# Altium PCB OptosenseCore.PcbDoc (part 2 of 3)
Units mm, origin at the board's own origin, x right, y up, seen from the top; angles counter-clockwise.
Board outline 65 x 56 mm, 4 copper layers (Top, Signal Layer 1, Power Layer 2, Bottom), stack 0.844 mm thick; 184 components, 119 nets, 728 pads, 633 vias.
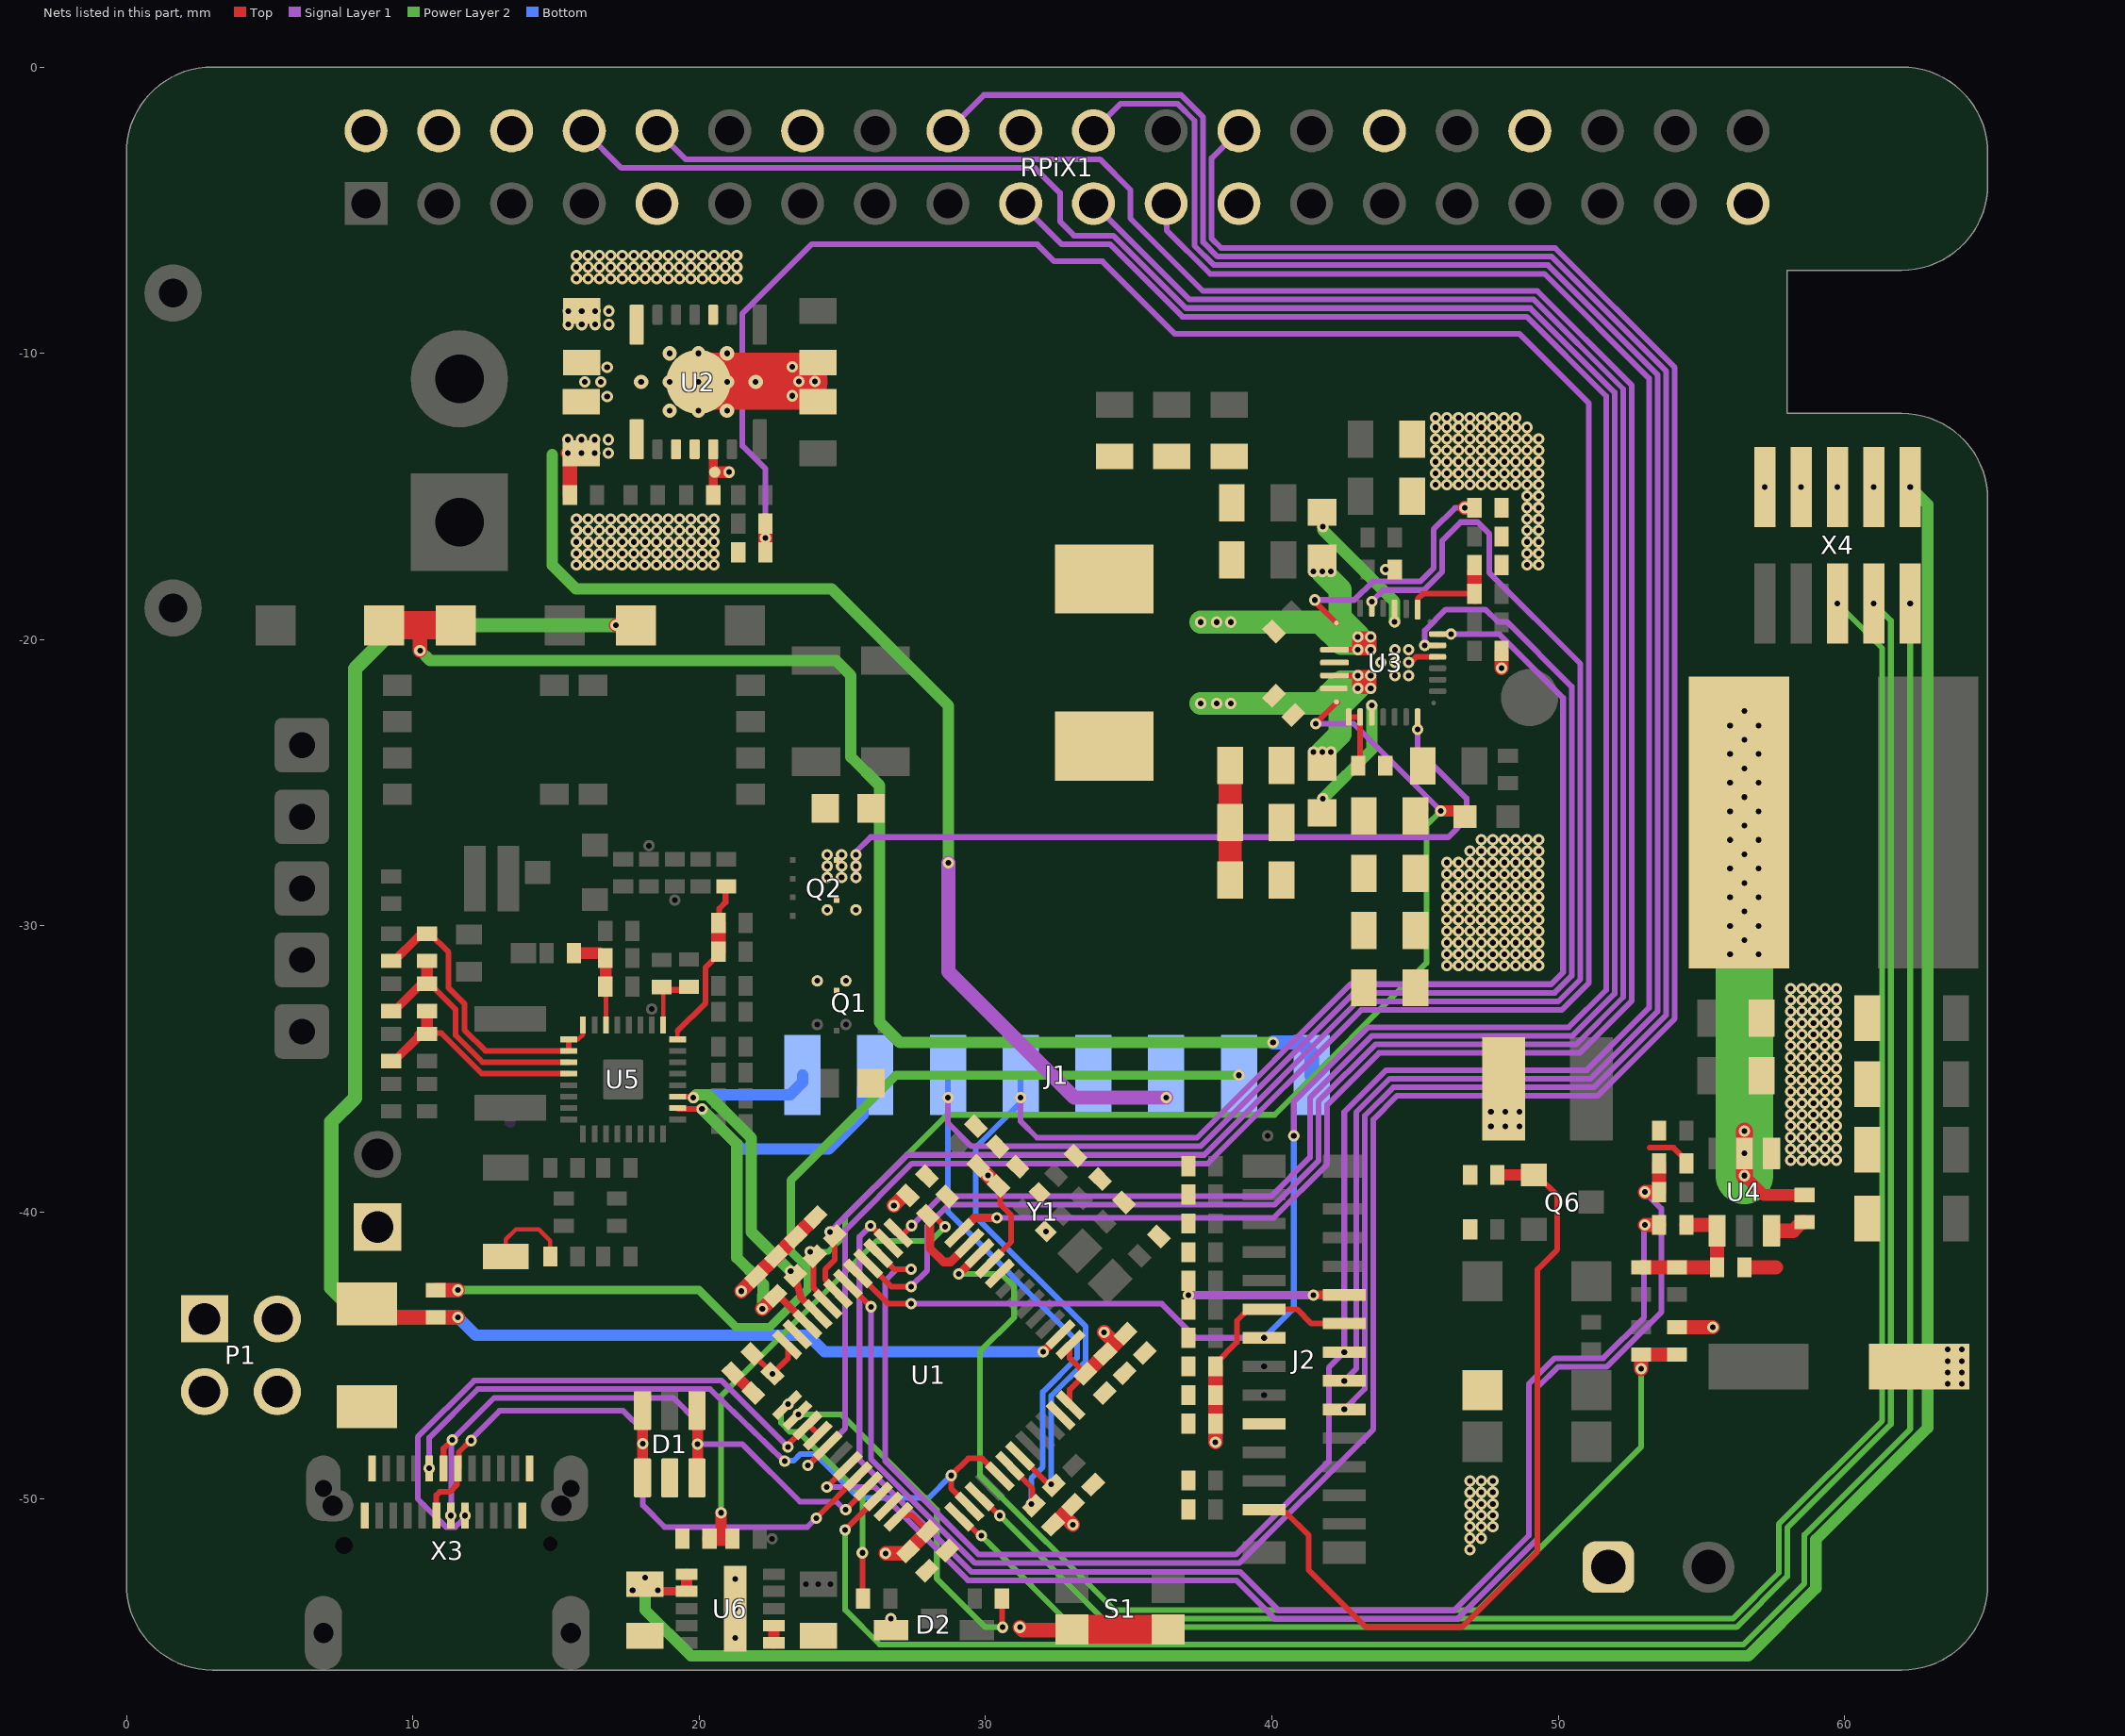
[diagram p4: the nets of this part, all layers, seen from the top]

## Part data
C1 C2 C3 C4 C5 C6 C7 C8 C9 C10 C11 C12 C13 C14 C15 C16 C24 C34 C35 C38 C41 C45 C48 C54 C55 C56 C57 C58 C59 C60 C61 C62 C64 C67 C68 C69 C70 C71 C72 C74: library part C_X_0402
C17 C18: library part C_X_0603
C19 C20 C21 C22 C25 C26 C27 C28 C29 C30 C31 C32 C33 C36 C37 C40 C42 C43 C44 C46 C47 C63 C65: library part C_X_0805
C49 C50 C51 C52: library part C_X_1206
C53: library part 865080543009, "WCAP-ASLI Aluminum Electrolytic Capacitor, V-Chip, SMT, D6.3xH5.5mm, 47uF, 35V", Capacitance Tolerance=+/-20%, Leakage Current=16.45uA, Manufacturer="Wurth Elektronik", Operating Temperature="-55 to +105degC", Rated Voltage=35VDC, Ripple Current=240mA
C66: library part C_X_1210
C73 C75 C76 C77 C78 C79 C80 C81 C82 C83: library part C_X_0402, "50V"
D1: "17V Clamp 5A _8/20Âµs_ Ipp Tvs Diode Surface Mount SOT-23-6", Package="SOT-23-6 STMicroelectronics"
D2: library part 155124RG73200, "WL-SBSW SMT Bi-color Side View Waterclear, size 1204, Red & Green, 120deg", Emitting Color="Red & Green", Forward Voltage="3.3V@Green, 2V@Red", Operating Temperature="-40 to +85degC"
D3 D4: library part D_Zener_SOD-80_12V, "12V BZT55C12-GS08"
D5: "Green 569nm LED Indication - Discrete 2.1V 0603 (1608 Metric)", Package="0603 Lite-On"
D6 D8 D9 D10 D11 D12: "BAT54W-HG3-08"
D7: library part D_Schottky_SOD323_BAS40WT
DZ1: "Zener Diode 3.3V 500mW Â±5% Surface Mount SOD-123", Package="SOD-123 Fairchild Semiconductor"
J2: library part 687324124422, "WR-FPC SMT ZIF Vertical, pitch 0.5mm, 24p", Contact Resistance=20mOhm, Operating Temperature="-25 to +85degC", Rated Current=0.5A, Working Voltage=50VAC
J_Interlock1: "WR-TBL Serie 1031 Horizontal Entry Modular, Pressure Clamp, THT, pitch 3.5mm, 2p", Manufacturer="Wurth Elektronik", Operating Temperature="-40 to +105degC", Rated Current [UL]=10A, Working Voltage [UL]=125VAC
L1: library part L_2u2_KEMET, "MPXV1D0630L2R2"
L2: library part L_18u, "744066180"
L3: library part 74404041680, "WE-LQS SMT Power Inductor, size 4012, 68µH, 0.45A, 1.495Ω", Case/Size Code=4012, DC Resistance=1.495Ω, Inductance=68µH, Manufacturer="Wurth Elektronik", Operating Temperature Max=125°C, Operating Temperature Min=-40°C, Rated Current=0.45A, Saturation Current=0.48A, Self Resonant Frequency=13MHz
NT1 NT2: library part "Net Tie"
P1: "WR-PHD Pin Header, THT, pitch 2.54mm, Dual Row, Vertical, 4p", Contact Resistance=20mOhm, Manufacturer="Wurth Elektronik", Operating Temperature="-40 to +105degC", Rated Current=3A, Withstanding Voltage=500VAC, Working Voltage=250VAC
P2: "WR-PHD Pin Header, THT, pitch 2.54mm, Single Row, Angled, 2p", Contact Resistance=20mOhm, Manufacturer="Wurth Elektronik", Operating Temperature="-40 to +105degC", Rated Current=3A, Withstanding Voltage=500VAC, Working Voltage=250VAC
Q1 Q2: "30V, N ch NexFET MOSFET, dual common source SON3x3, 21.9mOhm 8-VSON -55 to 150", Package="VSON-8 Texas Instruments"
Q3: library part Q_P-Channel_MOSFET_DMP3098LQ-7
Q4 Q5: library part Q_N-Channel_MOSFET_SO-8FL_NTMFS4C029NT1G
Q6: library part NTR4170NT1G
R1 R2 R3 R4 R5 R6 R7 R8 R9 R10 R11 R12 R13 R14 R15 R16 R17 R18 R19 R20 R21 R22 R23 R24 R25 R26 R27 R28 R29 R30 R31 R33 R34 R35 R36 R37 R38 R39 R40 R41 R42 R43 R44 R45 R46 R47 R48 R49 R50 R51 R52 R53 R54 R56 R57: library part R_X_0402
R32: library part R_X_0508
R55: library part R_X_1206
RPiX1: library part RPi, "WR-PHD Socket Header, SMT, pitch 2.54mm, Dual Row, Vertical, 40pin", Contact Resistance=20mOhm, Operating Temperature="-40 to +105degC", Part Number=61004021821, Rated Current=3A, Withstanding Voltage=600VAC, Working Voltage=250VAC
S1: "WS-TASV J-Bend SMT Tact Switch, 3.5x2.9x1.7mm, 350gf", Manufacturer="Wurth Elektronik", Operating Temperature="-40 to +85degC", Rated Current=50mA, Rated Voltage=12VDC
TP1: library part Testpoint, "Testpoint"
U1: library part STM32L552CCXX
U2: "No Description Available"
U3: library part BQ25792, "Battery Charger IC, QFN (29) _4x4_"
U4: library part IC_TPS54302
U5: library part IC_BQ40z80
U6: "4V to 36V, 1A Step-Down Converter Module With Integrated Inductor in 3x3.8x1.6mm Package 10-uSiP -40 to 125", Package=None
X1: library part X_XH5
X2: library part X_XT30PB-F-90°, "XT30PB-F-90°"
X3: library part X_USB_TypC
X4: library part X_Cortex_Debug_10
Y1: library part 830072539, "WE-XTAL Quartz Crystal, SMT, IQXC-26, 24MHz, +/-15ppm", Frequency Stability=+/-15ppm, Load Capacitance=8pF, Manufacturer="Wurth Elektronik", Operating Temperature="-20 to +70degC"
Y2: library part NX2012SA-32.768K-STD-MUB-1, "32.768kHz Â±20ppm Crystal 12.5pF 80 kOhms 2-SMD, No Lead", Package="SMD-2 NDK"

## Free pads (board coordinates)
  round 0.4 hole 0.2 mask+0: 3(10.575,-48.95) 3(11.325,-50.6) 3(11.825,-50.6) 3(17.678,-53.213) 3(18.11,-52.769) 3(18.25,-27.2) 3(18.346,-32.907) 3(18.561,-53.213) 3(19.15,-29.1) 3(19.8,-36) 3(20.1,-36.4) 3(20.764,-50.5) 3(21.475,-42.76) 3(22.207,-43.375) 3(22.548,-51.41) 3(22.56,-45.648) 3(22.987,-48.7) 3(23.1,-48.2) 3(23.11,-46.709) 3(23.195,-42.066) 3(23.464,-47.062) 3(23.724,-52.997) 3(23.879,-41.383) 3(24.165,-52.997) 3(24.574,-40.688) 3(24.587,-52.997) 3(25.1,-51.1) 3(26.508,-51.918) 3(26.802,-39.771) 3(28.69,-36) 3(30.081,-38.722) 3(31.23,-36) 3(33.055,-50.914) 3(34.145,-44.196) 3(37.515,-22.234) 3(37.515,-19.391) 3(38.071,-22.234) 3(38.071,-19.391) 3(38.563,-22.234) 3(38.563,-19.391) 3(38.85,-35.217) 3(39.73,-46.392) 3(39.73,-45.392) 3(39.73,-44.392) 3(39.853,-37.333) 3(40.042,-34.072) 3(40.767,-37.333) 3(41.453,-23.927) 3(41.453,-17.628) 3(41.758,-23.927) 3(41.758,-17.628) 3(41.783,-25.555) 3(41.783,-16.055) 3(42.062,-23.927) 3(42.062,-17.628) 3(42.53,-46.892) 3(42.53,-45.892) 3(42.53,-44.892) 3(43.004,-21.705) 3(43.004,-21.255) 3(43.004,-20.355) 3(43.004,-19.905) 3(43.451,-21.705) 3(43.451,-21.255) 3(43.451,-20.355) 3(43.451,-19.905) 3(43.488,-22.301) 3(44.288,-19.38) 3(45.339,-20.205) 3(46.253,-19.805) 3(47.65,-37) 3(47.65,-36.5) 3(48.15,-37) 3(48.15,-36.5) 3(48.65,-37) 3(48.65,-36.5)

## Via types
v1: diameter 0.4, hole 0.2, Top to Bottom, tented both sides, 616 vias
v2: diameter 0.5, hole 0.2, Top to Bottom, tented bottom, 11 vias
v3: diameter 4, hole 2.75, Top to Bottom, 4 vias
v4: diameter 0.4, hole 0.2, Top to Bottom, tented bottom, 1 vias
v5: diameter 0.6, hole 0.3, Top to Bottom, tented bottom, 1 vias

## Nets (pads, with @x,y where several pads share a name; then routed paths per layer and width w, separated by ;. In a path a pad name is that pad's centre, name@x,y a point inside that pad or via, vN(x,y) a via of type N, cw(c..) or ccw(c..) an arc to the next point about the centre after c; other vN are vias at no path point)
3V3: C7.2 C8.2 C9.2 C10.2 C11.2 C12.2 C13.2 C14.2 C15.2 C16.2 C63.2 C72.2 C73.2 C74.2 D2.2 J2.15 J2.16 L3.1 pad.3@17.678,-53.213 pad.3@18.11,-52.769 pad.3@18.561,-53.213 pad.3@21.475,-42.76 pad.3@22.56,-45.648 pad.3@26.508,-51.918 pad.3@26.802,-39.771 pad.3@30.081,-38.722 pad.3@33.055,-50.914 pad.3@34.145,-44.196 pad.3@47.65,-36.5 pad.3@47.65,-37 pad.3@48.15,-36.5 pad.3@48.15,-37 pad.3@48.65,-36.5 pad.3@48.65,-37 R5.1 R6.1 R7.1 R8.2 R9.1 R10.2 S1.2 S1.4 U1.1 U1.9 U1.24 U1.36 U1.48 U6.6 U6.7 X4.1 | length 119.9
  Top w0.2: C9.2@21.86,-44.948 C10.2@22.56,-45.648 23.11,-45.098 U1.24@23.11,-44.658 ; U1.36@26.999,-50.598 27.439,-50.598 C11.2@27.989,-51.148 ; U1.9@30.146,-41.794 30.9,-41.04 30.9,-40.102 30.522,-39.724 30.522,-39.31 C7.2@30.599,-39.232 ; U1.48@32.939,-46.709 32.939,-46.197 C13.2@33.489,-45.648 32.939,-45.098 U1.1@32.939,-44.658 ; C72.2@38.032,-45.39 38.032,-45.29 38.78,-44.542 38.78,-43.966 38.782,-43.964 38.782,-43.79 39.18,-43.392 40.88,-43.392 41.38,-43.892 J2.15@42.53,-43.892
  Top w0.3: C63.2@18.11,-52.997 18.36,-53.247 U6.7@19.56,-53.247 ; R6.1@23.323,-40.817 R6.1@23.332,-40.817
  Top w0.4: U6.7@19.56,-53.247 U6.6@19.56,-52.647
  Top w0.5: pad.3@21.477,-42.759 R10.2@21.989,-42.248 R9.1@22.689,-41.548 R6.1@23.323,-40.913 ; R6.1@23.421,-40.815 R7.1@24.056,-40.181 ; pad.3@26.508,-51.918 27.218,-51.918 C12.2@27.289,-51.848 27.918,-51.218 C11.2@27.989,-51.148 ; pad.3@26.803,-39.763 27.218,-39.349 C16.2@27.289,-39.419 ; C8.2@29.899,-38.532 pad.3@30.085,-38.718 ; pad.3@30.081,-38.722 30.089,-38.722 C7.2@30.452,-39.084 ; v1(31.2,-54.5) 31.3,-54.6 32.997,-54.6 S1.2@33.025,-54.572 ; R5.1@32.36,-50.919 32.431,-50.849 32.746,-50.534 ; pad.3@33.055,-50.914 32.746,-50.605 32.746,-50.534 ; R8.2@33.06,-50.219 32.746,-50.534 ; C13.2@33.489,-45.648 33.559,-45.577 C14.2@34.189,-44.948 34.543,-44.593 ; pad.3@34.145,-44.196 34.543,-44.593 ; C15.2@34.889,-44.248 34.543,-44.593 ; v1(38.032,-48.04) C74.2@38.032,-47.39 C73.2@38.032,-46.39 C72.2@38.032,-45.39
  Top w1: S1.2@33.025,-54.572 S1.4@36.375,-54.572
  Power Layer 2 w0.4: pad.3@18.11,-52.769 18.11,-53.894 19.716,-55.5 56.638,-55.5 59,-53.138 59,-51.438 62.9,-47.538 62.9,-15.28 v1(62.291,-14.671)
  other v1: 26.7,-54.2
5V1: C21.2 C22.2 J1.6 R15.2 RPiX1.2 RPiX1.4 U2.7 U2.8 | length 39.9
  Top w0.5: v1(15.416,-13.492) 15.487,-13.564 R15.2@15.487,-14.951
  Signal Layer 1 w0.5: v1(28.7,-27.8) 28.7,-31.6 33.1,-36 v1(36.31,-36)
  Power Layer 2 w0.4: 14.875,-13.545 14.875,-17.411 15.69,-18.226 24.616,-18.226 28.7,-22.31 v1(28.7,-27.8)
  other v1: 15.887,-13.492 16.358,-13.492 16.83,-13.492 15.416,-13.018 15.887,-13.018 16.358,-13.018 16.83,-13.018 15.428,-8.998 15.9,-8.998 16.371,-8.998 16.842,-8.998 15.428,-8.523 15.9,-8.523 16.371,-8.523 16.842,-8.523
A: D6.C D9.C J1.8 pad.3@40.042,-34.072 | length 47.6
  Top w0.5: v1(10.252,-20.382) 10.252,-19.5
  Top w1: D9.C@9.005,-19.5 10.253,-19.5 D6.C@11.5,-19.5
  Power Layer 2 w0.4: v1(10.252,-20.382) 10.602,-20.732 24.774,-20.732 25.3,-21.257 25.3,-24.1 26.3,-25.1 26.3,-33.368 27.004,-34.072 pad.3@40.042,-34.072
  Bottom w0.5: pad.3@40.042,-34.072 41.005,-34.072 41.39,-34.457 J1.8@41.39,-35.217
AGND_5V1: NT1.2 R19.1 U2.12 | length 1.5
  Top w0.3: R19.1@20.494,-14.951 20.494,-14.1 20.494,-14 U2.12@20.494,-13.479
B: J1.7 pad.3@38.85,-35.217 R43.2 | length 35.3
  Top w0.5: R43.2@10.8,-42.725 v1(11.575,-42.725)
  Power Layer 2 w0.3: v1(11.575,-42.725) 19.995,-42.725 21.294,-44.025 22.454,-44.025 23.8,-42.679 23.8,-41.956 23.2,-41.356 23.2,-38.893 26.876,-35.217 pad.3@38.85,-35.217
BUSY: J2.9 pad.3@42.53,-46.892 RPiX1.18 | length 77.2
  Signal Layer 1 w0.2: RPiX1.18@28.69,-2.23 29.94,-0.98 36.828,-0.98 37.6,-1.752 37.6,-6.122 38.101,-6.623 49.768,-6.623 53.771,-10.625 53.771,-33.114 51.245,-35.64 44.24,-35.64 43.245,-36.635 43.245,-46.176 pad.3@42.53,-46.892
CHARGER_VIN: C30.1 C31.1 C32.1 C33.1 C34.2 Q1.10 Q1.10.1 Q1.10.2 Q2.10 Q2.10.1 Q2.10.2 U3.2 U3.3 | length 3.3
  Top w0.2: U3.2@42.688,-22.705 U3.3@43.088,-22.705 43.088,-23.749 ; C34.2@43.088,-24.519 43.088,-23.749 ; U3.3@43.088,-22.679 43.088,-23.749
CHG_INT: pad.3@24.574,-40.688 R7.2 U1.19 U3.21 | length 55.2
  Top w0.2: R7.2@24.739,-40.841 24.668,-40.911 24.668,-41.123 24.739,-41.194 24.739,-41.661 24.4,-42 24.4,-42.342 24.842,-42.784 U1.19@24.842,-42.855
  Signal Layer 1 w0.2: pad.3@24.574,-40.688 25.03,-40.231 27.261,-38 37.637,-38 42.997,-32.64 50.002,-32.64 50.771,-31.872 50.771,-20.846 47.6,-17.675 47.6,-16.316 47.184,-15.9 46.594,-15.9 45.948,-16.546 45.948,-17.633 45.309,-18.272 43.891,-18.272 v1(43.488,-18.675)
D/C#: J2.11 pad.3@42.53,-45.892 RPiX1.22 | length 70.4
  Signal Layer 1 w0.2: RPiX1.22@33.77,-2.23 34.72,-1.28 36.704,-1.28 37.3,-1.876 37.3,-6.246 37.977,-6.923 49.644,-6.923 53.471,-10.75 53.471,-32.99 51.121,-35.34 44.115,-35.34 42.945,-36.51 42.945,-45.476 pad.3@42.53,-45.892
DIFF_USB_FS_N: D1.1 D1.6 U1.32 X3.A07 X3.B07 | length 23.7
  Top w0.2: X3.B07@10.825,-50.6 10.825,-49.886 10.942,-49.769 11.298,-49.769 11.541,-49.525 11.541,-48.983 X3.A07@11.575,-48.95 11.61,-48.915 11.61,-48.385 12.014,-47.981 v1(12.04,-47.981) ; v1(24.092,-50.686) 24.092,-50.677 U1.32@25.585,-49.184
  Top w0.381: D1.1@18.024,-49.283 D1.6@18.024,-46.933
  Signal Layer 1 w0.2: v1(12.04,-47.981) 12.04,-47.93 13.033,-46.937 17.346,-46.937 18.034,-47.625 v1(18.034,-48.082) 18.034,-50.241 18.796,-51.003 23.774,-51.003 v1(24.092,-50.686)
DIFF_USB_FS_P: D1.3 D1.4 pad.3@11.325,-50.6 U1.33 X3.A06 X3.B06 | length 24.2
  Top w0.2: X3.A06@11.075,-48.95 11.075,-48.259 v1(11.379,-47.955) ; X3.B06@11.29,-50.565 X3.B06@11.325,-50.6 ; v1(25.121,-50.394) 25.938,-49.576 U1.33@25.938,-49.537
  Top w0.381: D1.3@19.924,-48.903 D1.3@19.924,-49.283 19.947,-49.26 19.947,-46.956 D1.4@19.924,-46.933
  Signal Layer 1 w0.2: pad.3@11.325,-50.6 11.352,-50.572 11.352,-47.982 v1(11.379,-47.955) 11.379,-47.949 12.845,-46.483 19.102,-46.483 19.939,-47.32 v1(19.939,-48.108) 21.514,-48.108 23.52,-50.114 24.787,-50.114 25.066,-50.394 v1(25.121,-50.394)
External_Voltage_Source: C39.2 P1.3 P1.4 Q2.9 Q2.9.1 Q2.9.2 U3.8 | length 27.1
  Top w0.2: v1(45.085,-23.139) 45.088,-23.137 U3.8@45.088,-22.705
  Signal Layer 1 w0.2: v1@25.475,-28.414 Q2.9.2@25.475,-27.914 25.475,-27.414 25.989,-26.9 46.164,-26.9 46.8,-26.264 46.8,-25.549 45.085,-23.834 v1(45.085,-23.139)
  other v1: 24.475,-28.314 24.975,-28.314 25.475,-28.314 24.975,-27.914 24.475,-27.514 24.975,-27.514 25.475,-27.514
GDR: J2.2 Q6.B R57.2 | length 28.1
  Top w0.2: J2.2@39.73,-50.392 39.83,-50.492 40.492,-50.492 41.28,-51.28 41.28,-52.499 43.281,-54.5 46.624,-54.5 49.275,-51.849 49.275,-42 49.967,-41.308 49.967,-39.417 49.3,-38.75 Q6.B@49.3,-38.7
  Top w0.4: R57.2@47.95,-38.7 Q6.B@49.3,-38.7
GND: C1.1 C2.1 C3.1 C4.1 C5.1 C6.1 C7.1 C8.1 C9.1 C10.1 C11.1 C12.1 C13.1 C14.1 C15.1 C16.1 C19.2 C20.2 C21.1 C22.1 C23.1 C24.1 C25.2 C26.2 C27.2 C28.2 C29.2 C30.2 C31.2 C32.2 C33.2 C34.1 C35.1 C36.2 C37.2 C38.1 C39.1 C40.1 C41.1 C42.2 C43.2 C44.2 C46.2 C47.2 C48.1 C49.2 C50.2 C51.2 C52.2 C53.2 C63.1 C65.1 C72.1 C73.1 C74.1 C75.1 C76.1 C77.1 C78.1 C79.1 C80.1 C81.1 C82.1 C83.1 D1.2 D12.C DZ1.A J1.5 J2.8 J2.17 J_Interlock1.1 NT1.1 P1.1 P1.2 P2.1 R3.2 R4.2 R11.1 R18.2 R21.1 R25.1 R26.1 R29.2 R30.1 R54.1 R55.2 R56.1 R57.1 RPiX1.GND U1.8 U1.23 U1.35 U1.47 U2.3 U2.10 U2.11 U2.15 U3.13 U3.27 U4.1 U6.1 U6.2 U6.11 U6.11_1 U6.11_2 U6.11_3 X3.A01 X3.A12 X3.B01 X3.B12 X4.3 X4.5 X4.7 X4.9 Y1.2 Y1.4 | length 22.8
  Top w0.15: R55.2@13.25,-41.55 13.25,-40.95 13.6,-40.6 14.4,-40.6 14.8,-41 R54.1@14.8,-41.55
  Top w0.2: v1(44.78,-20.805) 44.834,-20.805 45.035,-20.605 U3.13@45.788,-20.605 ; 53.192,-37.75 54.025,-37.75 54.475,-38.2 R29.2@54.475,-38.3
  Top w0.3: v1@41.456,-42.892 J2.17@42.53,-42.892
  Top w0.4: C9.1@21.189,-45.619 C10.1@21.889,-46.319 ; U6.1@22.61,-55.047 U6.2@22.61,-54.447
  Top w0.5: v1(48.025,-21) R26.1@48.025,-20.4 ; R3.2@54.15,-44.025 v1(55.4,-44.025) ; R30.1@56.5,-41.925 57.6,-41.925
  Top w0.8: C44.2@38.542,-27.805 C43.2@38.542,-26.397 C42.2@38.542,-24.397 ; C33.2@45.014,-26.163 45.014,-25.975 C33.2@45.064,-25.925
  Top w2: v2(19.974,-11.004) 19.999,-10.979 v1(23.482,-10.979)
  Signal Layer 1 w0.3: v1(37.082,-42.9) v1(41.456,-42.9)
  other v1: 46.916,-51.791 46.916,-51.391 47.316,-51.391 46.916,-50.991 47.316,-50.991 47.716,-50.991 46.916,-50.591 47.316,-50.591 47.716,-50.591 46.916,-50.191 47.316,-50.191 47.716,-50.191 46.916,-49.791 47.316,-49.791 47.716,-49.791 46.916,-49.391 47.316,-49.391 47.716,-49.391 63.6,-46 64.1,-46 63.6,-45.6 64.1,-45.6 63.6,-45.2 64.1,-45.2 63.6,-44.8 64.1,-44.8 32.106,-40.672 58.116,-38.191 58.516,-38.191 58.916,-38.191 59.316,-38.191 59.716,-38.191 58.116,-37.791 58.516,-37.791 58.916,-37.791 59.316,-37.791 59.716,-37.791 58.116,-37.391 58.516,-37.391 58.916,-37.391 59.316,-37.391 59.716,-37.391 58.116,-36.991 58.516,-36.991 58.916,-36.991 59.316,-36.991 59.716,-36.991 58.116,-36.591 58.516,-36.591 58.916,-36.591 59.316,-36.591 59.716,-36.591 58.116,-36.191 58.516,-36.191 58.916,-36.191 59.316,-36.191 59.716,-36.191 58.116,-35.791 58.516,-35.791 58.916,-35.791 59.316,-35.791 59.716,-35.791 58.116,-35.391 58.516,-35.391 58.916,-35.391 59.316,-35.391 59.716,-35.391 58.116,-34.991 58.516,-34.991 58.916,-34.991 59.316,-34.991 59.716,-34.991 58.116,-34.591 58.516,-34.591 58.916,-34.591 59.316,-34.591 59.716,-34.591 58.116,-34.191 58.516,-34.191 58.916,-34.191 59.316,-34.191 59.716,-34.191 58.116,-33.791 58.516,-33.791 58.916,-33.791 59.316,-33.791 59.716,-33.791 58.116,-33.391 58.516,-33.391 58.916,-33.391 59.316,-33.391 59.716,-33.391 58.116,-32.991 58.516,-32.991 58.916,-32.991 59.316,-32.991 59.716,-32.991 58.116,-32.591 58.516,-32.591 58.916,-32.591 59.316,-32.591 59.716,-32.591 58.116,-32.191 58.516,-32.191 58.916,-32.191 59.316,-32.191 59.716,-32.191 46.116,-31.391 46.516,-31.391 46.916,-31.391 47.316,-31.391 47.716,-31.391 48.116,-31.391 48.516,-31.391 48.916,-31.391 49.316,-31.391 46.116,-30.991 46.516,-30.991 46.916,-30.991 47.316,-30.991 47.716,-30.991 48.116,-30.991 48.516,-30.991 48.916,-30.991 49.316,-30.991 46.116,-30.591 46.516,-30.591 46.916,-30.591 47.316,-30.591 47.716,-30.591 48.116,-30.591 48.516,-30.591 48.916,-30.591 49.316,-30.591 46.116,-30.191 46.516,-30.191 46.916,-30.191 47.316,-30.191 47.716,-30.191 48.116,-30.191 48.516,-30.191 48.916,-30.191 49.316,-30.191 46.116,-29.791 46.516,-29.791 46.916,-29.791 47.316,-29.791 47.716,-29.791 48.116,-29.791 48.516,-29.791 48.916,-29.791 49.316,-29.791 46.116,-29.391 46.516,-29.391 46.916,-29.391 47.316,-29.391 47.716,-29.391 48.116,-29.391 48.516,-29.391 48.916,-29.391 49.316,-29.391 46.116,-28.991 46.516,-28.991 46.916,-28.991 47.316,-28.991 47.716,-28.991 48.116,-28.991 48.516,-28.991 48.916,-28.991 49.316,-28.991 46.116,-28.591 46.516,-28.591 46.916,-28.591 47.316,-28.591 47.716,-28.591 48.116,-28.591 48.516,-28.591 48.916,-28.591 49.316,-28.591 46.116,-28.191 46.516,-28.191 46.916,-28.191 47.316,-28.191 47.716,-28.191 48.116,-28.191 48.516,-28.191 48.916,-28.191 49.316,-28.191 46.116,-27.791 46.516,-27.791 46.916,-27.791 47.316,-27.791 47.716,-27.791 48.116,-27.791 48.516,-27.791 48.916,-27.791 49.316,-27.791 46.916,-27.391 47.316,-27.391 47.716,-27.391 48.116,-27.391 48.516,-27.391 48.916,-27.391 49.316,-27.391 47.316,-26.991 47.716,-26.991 48.116,-26.991 48.516,-26.991 48.916,-26.991 49.316,-26.991 44.298,-21.255 44.777,-21.255 43.8,-20.805 44.298,-20.805 44.298,-20.355 44.777,-20.355 43.967,-17.551 15.716,-17.391 16.116,-17.391 16.516,-17.391 16.916,-17.391 17.316,-17.391 17.716,-17.391 18.116,-17.391 18.516,-17.391 18.916,-17.391 19.316,-17.391 19.716,-17.391 20.116,-17.391 20.516,-17.391 48.916,-17.391 49.316,-17.391 15.716,-16.991 16.116,-16.991 16.516,-16.991 16.916,-16.991 17.316,-16.991 17.716,-16.991 18.116,-16.991 18.516,-16.991 18.916,-16.991 19.316,-16.991 19.716,-16.991 20.116,-16.991 20.516,-16.991 48.916,-16.991 49.316,-16.991 15.716,-16.591 16.116,-16.591 16.516,-16.591 16.916,-16.591 17.316,-16.591 17.716,-16.591 18.116,-16.591 18.516,-16.591 18.916,-16.591 19.316,-16.591 19.716,-16.591 20.116,-16.591 20.516,-16.591 48.916,-16.591 49.316,-16.591 15.716,-16.191 16.116,-16.191 16.516,-16.191 16.916,-16.191 17.316,-16.191 17.716,-16.191 18.116,-16.191 18.516,-16.191 18.916,-16.191 19.316,-16.191 19.716,-16.191 20.116,-16.191 20.516,-16.191 48.916,-16.191 49.316,-16.191 15.716,-15.791 16.116,-15.791 16.516,-15.791 16.916,-15.791 17.316,-15.791 17.716,-15.791 18.116,-15.791 18.516,-15.791 18.916,-15.791 19.316,-15.791 19.716,-15.791 20.116,-15.791 20.516,-15.791 48.916,-15.791 49.316,-15.791 48.916,-15.391 49.316,-15.391 48.916,-14.991 49.316,-14.991 57.211,-14.671 58.481,-14.671 59.751,-14.671 61.021,-14.671 45.716,-14.591 46.116,-14.591 46.516,-14.591 46.916,-14.591 47.316,-14.591 47.716,-14.591 48.116,-14.591 48.516,-14.591 48.916,-14.591 49.316,-14.591 45.716,-14.191 46.116,-14.191 46.516,-14.191 46.916,-14.191 47.316,-14.191 47.716,-14.191 48.116,-14.191 48.516,-14.191 48.916,-14.191 49.316,-14.191 21.046,-14.152 45.716,-13.791 46.116,-13.791 46.516,-13.791 46.916,-13.791 47.316,-13.791 47.716,-13.791 48.116,-13.791 48.516,-13.791 48.916,-13.791 49.316,-13.791 45.716,-13.391 46.116,-13.391 46.516,-13.391 46.916,-13.391 47.316,-13.391 47.716,-13.391 48.116,-13.391 48.516,-13.391 48.916,-13.391 49.316,-13.391 45.716,-12.991 46.116,-12.991 46.516,-12.991 46.916,-12.991 47.316,-12.991 47.716,-12.991 48.116,-12.991 48.516,-12.991 48.916,-12.991 49.316,-12.991 45.716,-12.591 46.116,-12.591 46.516,-12.591 46.916,-12.591 47.316,-12.591 47.716,-12.591 48.116,-12.591 48.516,-12.591 48.916,-12.591 45.716,-12.25 46.116,-12.25 46.516,-12.25 46.916,-12.25 47.316,-12.25 47.716,-12.25 48.116,-12.25 48.516,-12.25 16.789,-11.506 23.253,-11.487 16.002,-10.998 16.561,-10.998 24.041,-10.979 16.789,-10.49 23.253,-10.471 15.716,-7.391 16.116,-7.391 16.516,-7.391 16.916,-7.391 17.316,-7.391 17.716,-7.391 18.116,-7.391 18.516,-7.391 18.916,-7.391 19.316,-7.391 19.716,-7.391 20.116,-7.391 20.516,-7.391 20.916,-7.391 21.316,-7.391 15.716,-6.991 16.116,-6.991 16.516,-6.991 16.916,-6.991 17.316,-6.991 17.716,-6.991 18.116,-6.991 18.516,-6.991 18.916,-6.991 19.316,-6.991 19.716,-6.991 20.116,-6.991 20.516,-6.991 20.916,-6.991 21.316,-6.991 15.716,-6.591 16.116,-6.591 16.516,-6.591 16.916,-6.591 17.316,-6.591 17.716,-6.591 18.116,-6.591 18.516,-6.591 18.916,-6.591 19.316,-6.591 19.716,-6.591 20.116,-6.591 20.516,-6.591 20.916,-6.591 21.316,-6.591
  other v2: 18.974,-12.004 19.974,-12.004 20.974,-12.004 17.974,-11.004 18.974,-11.004 20.974,-11.004 21.974,-11.004 18.974,-10.004 19.974,-10.004 20.974,-10.004
I2C_SCL: J1.3 pad.3@28.69,-36 pad.3@45.339,-20.205 R5.2 U1.42 U3.14 | length 62.3
  Top w0.2: U1.42@30.817,-48.83 31.636,-49.648 R5.2@31.636,-50.195 ; pad.3@45.339,-20.205 U3.14@45.788,-20.205
  Signal Layer 1 w0.2: pad.3@28.69,-36 28.69,-36.89 29.5,-37.7 37.513,-37.7 42.873,-32.34 49.878,-32.34 50.471,-31.747 50.471,-21.642 48.209,-19.38 47.89,-19.38 47.459,-18.95 46.074,-18.95 45.339,-19.685 pad.3@45.339,-20.205
  Bottom w0.2: J1.3@28.69,-35.217 pad.3@28.69,-36 28.69,-39.99 33.2,-44.5 33.2,-45.083 32,-46.283 32,-48.9 31.6,-49.3 v1(31.6,-50.2)
I2C_SDA: J1.4 pad.3@31.23,-36 pad.3@46.253,-19.805 R8.1 U1.43 U3.15 | length 55.9
  Top w0.2: U1.43@31.171,-48.477 U1.43@31.206,-48.512 32.189,-49.495 R8.1@32.336,-49.495 ; U3.15@45.788,-19.805 pad.3@46.253,-19.805
  Signal Layer 1 w0.2: pad.3@31.23,-36 31.23,-36.83 31.8,-37.4 37.389,-37.4 42.748,-32.04 49.754,-32.04 50.171,-31.623 50.171,-22.038 47.937,-19.805 pad.3@46.253,-19.805
  Bottom w0.2: J1.4@31.23,-35.217 pad.3@31.23,-36 31.23,-36.172 30.695,-36.707 30.693,-36.707 29.654,-37.746 29.654,-40.154 33.5,-44 33.5,-45.207 32.3,-46.407 v1(32.3,-49.5)
ILIM_CHG: R23.1 R25.2 U3.17 | length 3.3
  Top w0.2: U3.17@45.088,-18.955 45.088,-18.59 45.278,-18.4 R23.1@47.075,-18.4
  Top w0.5: R23.1@47.075,-18.5 R25.2@47.075,-17.6
IO.PA0: R2.1 R3.1 U1.10 | length 42.1
  Top w0.3: v1(29.07,-42.163) U1.10@29.792,-41.441
  Top w0.5: v1(52.9,-45.475) R2.1@52.9,-44.975 R3.1@54.15,-44.975
  Power Layer 2 w0.2: v1(29.07,-42.163) 29.078,-42.163 30.563,-42.163 31,-42.6 31,-43.677 29.803,-44.874 29.803,-49.203 34.5,-53.9 47.2,-53.9 52.9,-48.2 v1(52.9,-45.475)
IO.PA1: C3.2 pad.3@20.764,-50.5 R1.1 R4.1 U1.11 | length 19.7
  Top w0.2: C3.2@27.989,-40.119 28.201,-40.119 28.201,-40.128 28.582,-40.51 v1(28.591,-40.51)
  Top w0.3: C3.2@28.059,-40.19 28.059,-41.258 28.54,-41.739 28.787,-41.739 U1.11@29.439,-41.087
  Top w0.4: 20.764,-51.41 pad.3@20.764,-50.5
  Top w0.5: R4.1@20.363,-51.41 20.764,-51.41 R1.1@21.166,-51.41
  Power Layer 2 w0.2: pad.3@20.764,-50.5 20.764,-46.435 26.2,-41 28.101,-41 v1(28.591,-40.51)
IO.PA2: RPiX1.10 U1.12 | length 87.9
  Top w0.3: U1.12@29.085,-40.734 29.619,-40.2 v1(30.4,-40.2)
  Signal Layer 1 w0.2: RPiX1.10@18.53,-2.23 19.525,-3.225 33.993,-3.225 35.06,-4.292 35.06,-5.288 37.595,-7.823 49.271,-7.823 52.571,-11.122 52.571,-32.617 50.748,-34.44 43.743,-34.44 41.93,-36.253 41.93,-38.336 40.066,-40.2 v1@30.346,-40.2
IO.PA3: RPiX1.8 U1.13 | length 91.1
  Top w0.2: U1.13@26.964,-40.734 27.026,-40.796 27.097,-40.796 v1(27.422,-40.47)
  Signal Layer 1 w0.2: RPiX1.8@15.99,-2.23 17.285,-3.525 31.725,-3.525 32.6,-4.4 32.6,-5.4 33.09,-5.89 34.466,-5.89 36.998,-8.423 49.023,-8.423 51.971,-11.371 51.971,-32.369 50.499,-33.84 43.494,-33.84 41.33,-36.004 41.33,-38.087 39.973,-39.445 28.448,-39.445 v1(27.422,-40.47)
IO.PA4: R31.1 U1.14 | length 49.9
  Top w0.2: v1(25.989,-40.474) 25.993,-40.474 26.607,-41.087 U1.14@26.61,-41.087
  Top w0.5: v1(53.025,-40.45) R31.1@53.525,-40.45
  Signal Layer 1 w0.2: v1(25.989,-40.474) 25.6,-40.863 25.6,-48.653 29.508,-52.56 38.885,-52.56 40.233,-53.909 46.361,-53.909 48.971,-51.299 48.971,-46.005 49.876,-45.1 51.576,-45.1 53,-43.676 53,-40.475 v1(53.025,-40.45)
IO.PA5: J2.13 pad.3@42.53,-44.892 RPiX1.23 U1.15 | length 93.5
  Top w0.2: U1.15@26.292,-41.476 U1.15@26.257,-41.441 26.816,-42 v1(27.4,-42)
  Signal Layer 1 w0.2: v1(27.4,-42) 26.89,-42 26.5,-42.39 26.5,-48.7 29.76,-51.96 38.74,-51.96 41.991,-48.709 41.991,-45.431 pad.3@42.53,-44.892 42.53,-36.502 43.991,-35.04 50.996,-35.04 53.171,-32.866 53.171,-10.874 49.52,-7.223 37.843,-7.223 36.324,-5.703 36.324,-4.784 RPiX1.23@36.31,-4.77
IO.PA6: RPiX1.21 U1.16 | length 75.4
  Top w0.2: U1.16@25.938,-41.83 26.709,-42.6 v1(27.4,-42.6)
  Signal Layer 1 w0.2: v1(27.4,-42.6) 27.969,-42.031 27.969,-40.485 28.71,-39.745 40.097,-39.745 41.63,-38.212 41.63,-36.129 43.618,-34.14 50.624,-34.14 52.271,-32.493 52.271,-11.247 49.147,-8.123 37.123,-8.123 RPiX1.21@33.77,-4.77
IO.PA7: J2.14 pad.3@39.73,-44.392 pad.3@40.767,-37.333 RPiX1.19 U1.17 | length 80.2
  Top w0.2: U1.17@25.585,-42.183 26.602,-43.2 v1(27.4,-43.2)
  Signal Layer 1 w0.2: v1(27.4,-43.2) 36.155,-43.2 37.347,-44.392 pad.3@39.73,-44.392 ; RPiX1.19@31.23,-4.77 32.65,-6.19 34.341,-6.19 36.874,-8.723 48.899,-8.723 51.671,-11.495 51.671,-32.244 50.375,-33.54 43.37,-33.54 40.767,-36.143 pad.3@40.767,-37.333
  Bottom w0.2: pad.3@39.73,-44.392 40.767,-43.354 pad.3@40.767,-37.333
IO.PA8: R16.2 R18.1 U1.29 | length 101.7
  Top w0.2: v1(23.8,-48.847) U1.29@24.524,-48.123
  Top w0.5: R18.1@22.319,-16.951 v1(22.319,-16.451) R16.2@22.319,-15.951 R16.2@22.319,-15.851
  Signal Layer 1 w0.2: v1(22.319,-16.451) 22.319,-14.039 21.514,-13.233 21.514,-8.611 23.927,-6.198 31.809,-6.198 32.401,-6.79 34.08,-6.79 36.613,-9.323 48.65,-9.323 51.071,-11.744 51.071,-31.996 50.127,-32.94 43.121,-32.94 37.762,-38.3 27.434,-38.3 25.1,-40.634 25.1,-47.547 v1(23.8,-48.847)
IO.PA10: R28.2 R29.1 U1.31 | length 45.6
  Top w0.2: v1(24.462,-49.6) U1.31@25.196,-48.866 U1.31@25.231,-48.83
  Top w0.5: v1(53.025,-39.3) R28.2@53.525,-39.3 R29.1@53.525,-38.3
  Signal Layer 1 w0.2: v1(24.462,-49.6) 26.123,-49.6 29.383,-52.86 38.76,-52.86 40.109,-54.209 46.113,-54.209 46.485,-54.209 49.271,-51.423 49.271,-51.051 49.271,-46.129 50,-45.4 51.7,-45.4 53.6,-43.5 53.6,-39.875 v1(53.025,-39.3)
IO.PA13: pad.3@25.1,-51.1 U1.34 X4.2 | length 75.1
  Top w0.2: pad.3@25.1,-51.1 26.292,-49.908 U1.34@26.292,-49.891
  Power Layer 2 w0.2: pad.3@25.1,-51.1 25.1,-53.9 26.3,-55.1 56.473,-55.1 58.6,-52.973 58.6,-51.273 62.291,-47.581 v1@62.291,-18.75
  other v1: 62.291,-18.741
IO.PA14: U1.37 X4.4 | length 67
  Top w0.2: U1.37@29.05,-50.598 29.1,-50.598 29.802,-51.3 v1(29.852,-51.3)
  Power Layer 2 w0.2: v1(29.852,-51.3) 30.226,-51.674 33.052,-54.5 56.224,-54.5 58,-52.724 58,-51.024 61.616,-47.408 61.616,-19.336 v1(61.021,-18.741)
IO.PA15: pad.3@10.575,-48.95 pad.3@22.987,-48.7 U1.38 U1.41 X3.A05 | length 25.6
  Top w0.2: U1.38@29.439,-50.28 28.8,-49.641 v1(28.8,-49.2) 29.4,-48.6 29.88,-48.6 U1.41@30.499,-49.219
  Signal Layer 1 w0.2: pad.3@10.575,-48.95 10.575,-47.876 12.268,-46.183 20.386,-46.183 pad.3@22.987,-48.7
  Bottom w0.2: pad.3@22.987,-48.7 23.006,-48.68 23.305,-48.68 23.538,-48.447 24.047,-48.447 25.587,-49.987 28.013,-49.987 v1(28.8,-49.2)
IO.PB0: RPiX1.26 U1.18 | length 95.1
  Top w0.2: U1.18@25.231,-42.537 v1(26,-43.306)
  Signal Layer 1 w0.2: v1(26,-43.306) 26,-48.624 29.636,-52.26 38.864,-52.26 43.545,-47.579 43.545,-36.759 44.364,-35.94 51.369,-35.94 54.071,-33.239 54.071,-10.501 49.893,-6.323 38.225,-6.323 37.9,-5.998 37.9,-3.18 RPiX1.26@38.85,-2.23
IO.PB2: D5.C pad.3@23.879,-41.383 R6.2 U1.20 U3.1 | length 41.2
  Top w0.2: R6.2@24.044,-41.536 23.973,-41.607 23.973,-41.819 24,-41.846 24,-42.649 24.489,-43.138 U1.20@24.489,-43.209 ; v1(41.529,-22.936) 42.257,-22.209 U3.1@42.257,-22.174 U3.1@42.288,-22.205
  Top w0.4: v1(45.901,-25.986) v1(45.901,-25.986) 46.548,-25.987 D5.C@46.748,-26.187
  Signal Layer 1 w0.2: v1(41.529,-22.936) 42.851,-22.936 v1(45.901,-25.986)
  Power Layer 2 w0.2: pad.3@23.879,-41.383 24.517,-41.383 25.1,-40.8 25.1,-40.156 28.656,-36.6 40.1,-36.6 45.4,-31.3 45.4,-26.487 v1(45.901,-25.986)
IO.PB3: U1.39 X4.6 | length 66.3
  Top w0.2: U1.39@29.792,-49.926 29.809,-49.926 30.483,-50.6 v1(30.5,-50.6)
  Power Layer 2 w0.2: v1(30.5,-50.6) 34.1,-54.2 56.1,-54.2 57.7,-52.6 57.7,-50.9 61.316,-47.284 61.316,-20.306 v1(59.751,-18.741)
IO.PB10: J1.1 pad.3@19.8,-36 pad.3@23.195,-42.066 R9.2 U1.21 U5.19 | length 14.4
  Top w0.2: U5.19@19.246,-35.966 19.766,-35.966 pad.3@19.8,-36
  Top w0.254: R9.2@23.36,-42.219 23.373,-42.38 23.389,-42.396 23.555,-42.982 23.611,-43.037 U1.21@24.135,-43.562
  Power Layer 2 w0.4: pad.3@19.8,-36 19.9,-35.9 20.307,-35.9 21.818,-37.411 21.818,-40.69 pad.3@23.195,-42.066
  Bottom w0.4: pad.3@19.8,-36 19.9,-35.9 23.175,-35.9 23.61,-35.465 J1.1@23.61,-35.217
IO.PB11: J1.2 pad.3@20.1,-36.4 pad.3@22.207,-43.375 R10.1 U1.22 U5.18 | length 19.1
  Top w0.2: U5.18@19.246,-36.366 19.246,-36.4 19.966,-36.4 20,-36.366 20.066,-36.366 pad.3@20.1,-36.4
  Top w0.254: R10.1@22.838,-42.972 U1.22@23.782,-43.916 U1.22@23.817,-43.951
  Top w0.5: pad.3@22.207,-43.375 22.207,-43.372 R10.1@22.66,-42.919
  Power Layer 2 w0.4: pad.3@20.1,-36.4 21.318,-37.618 21.318,-41.594 22.1,-42.376 22.24,-42.516 22.24,-42.691 pad.3@22.207,-43.375
  Bottom w0.4: pad.3@20.1,-36.4 21.5,-37.8 24.522,-37.8 25.715,-36.607 25.715,-35.652 J1.2@26.15,-35.217
IO.PB12: pad.3@23.11,-46.709 R12.1 U1.25 | length 8.3
  Top w0.2: v1(25.7,-51.9) 25.713,-51.913 25.713,-53.488 R12.1@25.725,-53.5
  Power Layer 2 w0.2: pad.3@23.11,-46.709 22.86,-46.959 22.86,-47.362 23.177,-47.678 23.478,-47.678 25.7,-49.9 v1(25.7,-51.9)
IO.PB13: pad.3@23.464,-47.062 R13.1 U1.26 | length 12.6
  Top w0.2: R13.1@30.575,-53.5 30.588,-53.512 30.588,-54.488 v1(30.6,-54.5)
  Power Layer 2 w0.2: pad.3@23.464,-47.062 24.962,-47.062 28.3,-50.4 28.3,-52.8 30,-54.5 v1(30.6,-54.5)
IO.PB14: pad.3@11.825,-50.6 pad.3@23.1,-48.2 U1.27 U1.28 X3.B05 | length 20.7
  Top w0.2: pad.3@23.1,-48.2 23.1,-48.133 23.817,-47.416 U1.28@24.171,-47.77
  Signal Layer 1 w0.2: pad.3@11.825,-50.6 11.825,-50.654 11.725,-50.754 11.725,-50.765 11.491,-51 11.159,-51 10.175,-50.015 10.175,-47.852 12.144,-45.883 20.783,-45.883 23.076,-48.176 pad.3@23.124,-48.176
IO.PC13: D8.A DZ1.C R43.1 U1.2 | length 62.1
  Top w0.3: v1(32.02,-44.877) 32.02,-44.87 U1.2@32.621,-44.269
  Top w0.5: DZ1.C@8.77,-43.2 9.245,-43.675 R43.1@10.8,-43.675 v1(11.575,-43.675) ; v1(17.1,-19.5) D8.A@17.795,-19.5
  Power Layer 2 w0.5: v1(11.575,-43.675) 8.175,-43.675 7.155,-42.655 7.155,-36.845 7.986,-36.014 7.986,-21.014 9.5,-19.5 v1(17.1,-19.5)
  Bottom w0.4: v1(11.575,-43.675) 12.2,-44.3 23.8,-44.3 24.377,-44.877 v1(32.02,-44.877)
NetC17_1: C17.1 pad.3@41.783,-25.555 pad.3@43.488,-22.301 U3.4 | length 4
  Power Layer 2 w0.4: pad.3@41.783,-25.555 43.488,-23.851 pad.3@43.488,-22.301
NetC17_2: C17.2 L1.1 pad.3@37.515,-22.234 pad.3@38.071,-22.234 pad.3@38.563,-22.234 pad.3@41.453,-23.927 pad.3@41.758,-23.927 pad.3@42.062,-23.927 pad.3@43.004,-21.255 pad.3@43.004,-21.705 pad.3@43.451,-21.255 pad.3@43.451,-21.705 U3.28 | length 12
  Top w0.2: U3.28@42.188,-21.255 pad.3@43.004,-21.255
  Top w0.4: pad.3@43.451,-21.255 pad.3@43.004,-21.255 pad.3@43.004,-21.705 ; pad.3@43.004,-21.705 43.451,-21.258 pad.3@43.451,-21.705 pad.3@43.004,-21.705
  Power Layer 2 w0.8: pad.3@37.515,-22.234 pad.3@38.071,-22.234 pad.3@38.563,-22.234 41.677,-22.234 42.425,-21.487 43.206,-21.487 ; pad.3@41.758,-23.927 42.381,-23.304 42.381,-22.328 pad.3@43.004,-21.705
NetC18_1: C18.1 pad.3@41.783,-16.055 pad.3@44.288,-19.38 U3.19 | length 4.4
  Power Layer 2 w0.4: pad.3@41.783,-16.055 41.783,-16.175 44.283,-18.675 44.283,-19.376 pad.3@44.288,-19.38
NetC18_2: C18.2 L1.2 pad.3@37.515,-19.391 pad.3@38.071,-19.391 pad.3@38.563,-19.391 pad.3@41.453,-17.628 pad.3@41.758,-17.628 pad.3@42.062,-17.628 pad.3@43.004,-19.905 pad.3@43.004,-20.355 pad.3@43.451,-19.905 pad.3@43.451,-20.355 U3.26 | length 12
  Top w0.2: U3.26@42.188,-20.355 pad.3@43.004,-20.355
  Top w0.4: pad.3@43.004,-20.351 pad.3@43.004,-19.905 pad.3@43.451,-19.905 pad.3@43.451,-19.908 ; pad.3@43.451,-19.908 pad.3@43.004,-20.355 pad.3@43.451,-20.355 pad.3@43.451,-19.908
  Power Layer 2 w0.8: pad.3@37.515,-19.391 pad.3@38.071,-19.391 41.677,-19.391 42.425,-20.139 43.206,-20.139 ; pad.3@41.758,-17.628 42.381,-18.251 42.381,-19.226 pad.3@43.004,-19.85
NetC38_2: C38.2 U3.24 | length 8.7
  Top w0.2: v1@41.58,-18.747 U3.24@42.257,-19.424
  Top w0.5: v1(46.736,-15.4) C38.2@47.075,-15.4
  Signal Layer 1 w0.2: v1(41.504,-18.618) 42.882,-18.618 43.528,-17.972 45.185,-17.972 45.648,-17.509 45.648,-16.152 46.4,-15.4 v1(46.736,-15.4)
NetC41_2: C41.2 C42.1 C43.1 C44.1 U3.29 | length 0.1
  Top w0.4: C42.1@40.342,-24.397 C42.1@40.392,-24.347
NetC45_1: C45.1 U4.6 | length 1.3
  Top w0.5: U4.6@57.45,-40.65 58.207,-40.65 58.5,-40.357 58.5,-40.35 C45.1@58.6,-40.35
NetC45_2: C45.2 L2.1 U4.2 | length 23.9
  Top w0.254: L2.1@56.314,-26.391 56.314,-22.686 v1(56.5,-22.5)
  Top w0.4: v1(56.5,-38.725) 57.175,-39.4 C45.2@58.6,-39.4
  Top w0.6: v1(56.5,-38.725) v1(56.5,-37.95) v1(56.5,-37.175)
  Power Layer 2 w2: v1(56.5,-38.725) v1(56.5,-37.95) v1(56.5,-37.175) 56.5,-31 v1(56.5,-30.5) 56.5,-30 v1(56.5,-29.5) 56.5,-29 v1(56.5,-28.5) 56.5,-28 v1(56.5,-27.5) v1(56.5,-26.5) v1(56.5,-25.5) v1(56.5,-24.5) 56.5,-24 v1(56.5,-23.5) 56.5,-22.7
  other v1: 56,-31 57,-31 56,-30 57,-30 56,-29 57,-29 56,-28 57,-28 56,-27 57,-27 56,-26 57,-26 56,-25 57,-25 56,-24 57,-24 56,-23 57,-23
NetC54_1: C54.1 R27.1 R30.2 R31.2 U4.4 | length 5.2
  Top w0.5: C54.1@52.9,-41.925 R27.1@54.15,-41.925 R30.2@55.55,-41.925 55.55,-41.825 U4.4@55.55,-40.65 55.55,-40.5 55.5,-40.45 R31.2@54.475,-40.45
NetC55_1: C55.1 C56.1 R35.1 U5.24 | length 7
  Top w0.152: U5.24@19.246,-33.966 19.246,-33.671
  Top w0.2: 19.246,-33.671 20.225,-32.692 20.225,-31.45 20.7,-30.975 20.7,-29.4 20.923,-29.177 R35.1@20.923,-28.7
  Top w0.5: C56.1@20.675,-30.9 C55.1@20.675,-29.9
NetC57_2: C57.2 R37.1 U5.25 | length 2.3
  Top w0.152: C57.2@18.581,-32.137 C57.2@18.689,-32.137 ; U5.25@18.746,-33.466 C57.2@18.746,-32.194
  Top w0.2: C57.2@18.689,-32.137 18.746,-32.194 18.789,-32.237 R37.1@19.595,-32.237
NetC58_1: C58.1 C59.1 R41.1 U5.30 | length 3.5
  Top w0.152: U5.30@16.741,-33.46 U5.30@16.746,-33.466 16.746,-32.252 C59.1@16.741,-32.246
  Top w0.4: R41.1@15.7,-30.951 16.538,-30.951 16.591,-31.004 16.691,-31.004 16.741,-31.054 16.741,-31.154 C59.1@16.741,-32.069 ; C59.1@16.725,-32.303 C59.1@16.725,-32.125
NetC60_1: C60.1 C61.2 R44.2 U5.3 | length 9.1
  Top w0.2: C61.2@10.5,-32.025 10.6,-32.025 11.5,-32.925 11.5,-33.826 12.44,-34.766 U5.3@15.446,-34.766
  Top w0.3: R44.2@9.35,-32.975 10.25,-32.075 C61.2@10.45,-32.075
  Top w0.4: R44.2@9.25,-32.975 R44.2@9.35,-32.975 ; C61.2@10.45,-32.075 C61.2@10.5,-32.025 C60.1@10.5,-31.225
NetC60_2: C60.2 R42.2 U5.1 U5.2 U5.32 | length 10.9
  Top w0.152: U5.1@15.446,-33.966 15.776,-33.966 15.946,-33.796 U5.32@15.946,-33.466
  Top w0.2: C60.2@10.5,-30.275 10.6,-30.275 11.25,-30.925 11.25,-32.168 11.8,-32.718 11.8,-33.633 12.533,-34.366 U5.2@15.446,-34.366 U5.1@15.446,-33.966 ; C60.2@10.75,-30.275 C60.2@10.75,-30.175
  Top w0.3: R42.2@9.25,-31.225 9.35,-31.225 10.2,-30.375 10.4,-30.375 C60.2@10.5,-30.275
NetC61_1: C61.1 C62.2 R45.2 U5.4 | length 8
  Top w0.2: C62.2@10.5,-33.775 10.525,-33.75 11,-33.75 12.416,-35.166 U5.4@15.446,-35.166
  Top w0.3: R45.2@9.35,-34.725 C62.2@10.25,-33.825
  Top w0.4: R45.2@9.25,-34.725 R45.2@9.35,-34.725 ; C62.2@10.25,-33.825 10.45,-33.825 C62.2@10.5,-33.775 C61.1@10.5,-32.975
